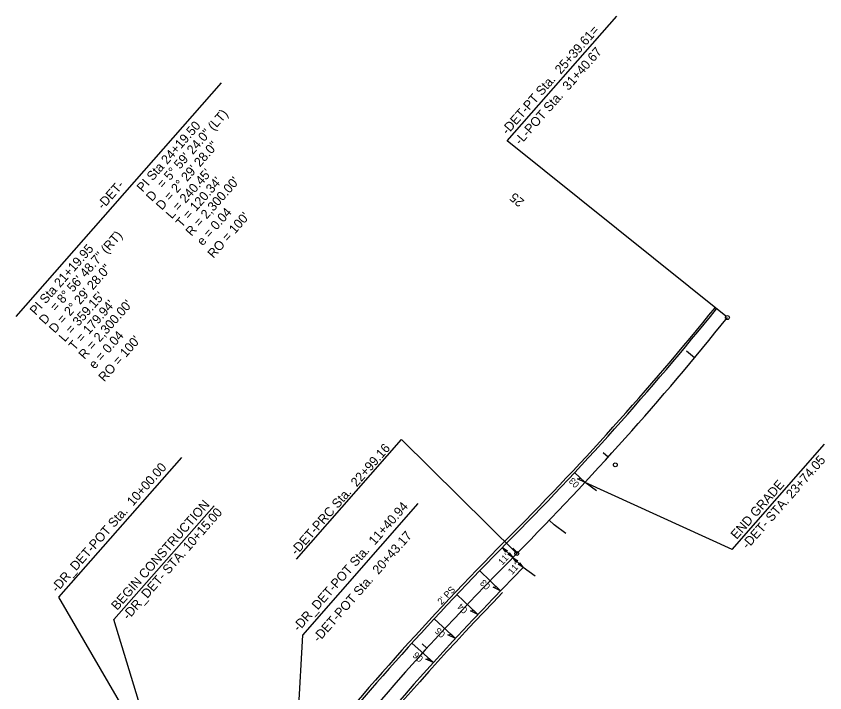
# Model space of a CAD drawing. Extents: x 2189637 to 2190858, y 386969 to 388736.
# Drawn here: x 2190244 to 2190858, y 388222 to 388736 of the extents above; entities that cross this region are included whole.
import ezdxf

# ---------------------------------------------------------------- set-up
doc = ezdxf.new("R2010")
doc.units = 0
for name, color, linetype in [('Exist Environmental Wetland Boundary', 7, 'Continuous'), ('Exist Environmental Wetland Boundary Cogo Comment', 7, 'Continuous'), ('Exist Environmental Wetland Boundary Cogo Point CELL', 7, 'Continuous'), ('Exist Horizontal Alignment Tick Label', 7, 'Continuous'), ('Exist Hydro Stream or Body of Water Leader', 7, 'Continuous'), ('Exist Hydro Swamp or Marsh', 7, 'Continuous'), ('Exist Property Corner CELL', 7, 'Continuous'), ('Exist Property Corner Cogo Elevation', 7, 'Continuous'), ('Exist Property Iron Pin CELL', 7, 'Continuous'), ('Exist Property Iron Pin Cogo Elevation', 7, 'Continuous'), ('Exist Property Iron Pin Cogo Number', 7, 'Continuous'), ('Exist Property Iron Pin Text', 7, 'Continuous'), ('Exist Roads EOP', 7, 'Continuous'), ('Exist Roads EOT', 7, 'Continuous'), ('Exist Roads Soil', 7, 'Continuous'), ('Prop Parcel Number Text', 7, 'Continuous')]:
    doc.layers.add(name, color=color, linetype=linetype)

msp = doc.modelspace()

# ---------------------------------------------------------------- linework, layer by layer
at = {"layer": 'Exist Environmental Wetland Boundary'}
msp.add_line((2190243.96, 388508.09), (2190399.95, 388685.52), dxfattribs=at)
at = {"layer": 'Exist Environmental Wetland Boundary Cogo Comment'}
for p, q in [((2190685.02, 388375.58), (2190676.22, 388381.92)), ((2190649.01, 388353.11), (2190652.7, 388349.56)), ((2190649.01, 388353.11), (2190652.7, 388349.56)), ((2190661.63, 388343.13), (2190652.7, 388349.56)), ((2190638.23, 388310.69), (2190629.25, 388317.16))]:
    msp.add_line(p, q, dxfattribs=at)
at = {"layer": 'Exist Environmental Wetland Boundary Cogo Point CELL'}
for centre, start, end in [((2188990.81, 389946.97), 315.25499, 321.24499), ((2192257.95, 386708.79), 135.25499, 144.20184)]:
    msp.add_arc(centre, 2300, start, end, dxfattribs=at)
at = {"layer": 'Exist Horizontal Alignment Tick Label'}
for p, q in [((2190693.78, 388401.04), (2190690.07, 388404.4)), ((2190624.97, 388328.48), (2190621.42, 388332)), ((2190556.12, 388255.97), (2190552.42, 388259.33))]:
    msp.add_line(p, q, dxfattribs=at)
at = {"layer": 'Exist Hydro Stream or Body of Water Leader'}
msp.add_line((2190759.36, 388476.52), (2190753.21, 388481.63), dxfattribs=at)
at = {"layer": 'Exist Hydro Swamp or Marsh'}
for centre, radius, start, end in [((2188993.22, 389949.67), 2289.19, 315.16471, 321.15472), ((2192257.95, 386708.79), 2311, 135.25499, 141.00543), ((2192257.95, 386708.79), 2289, 135.35973, 144.20184)]:
    msp.add_arc(centre, radius, start, end, dxfattribs=at)
at = {"layer": 'Exist Property Corner CELL'}
for centre, radius, start, end in [((2188997.2, 389954.14), 2287.53, 315.01487, 321.00487), ((2192257.95, 386708.79), 2313, 135.25499, 141.26353), ((2192257.95, 386708.79), 2287, 135.97689, 144.20184)]:
    msp.add_arc(centre, radius, start, end, dxfattribs=at)
at = {"layer": 'Exist Property Corner Cogo Elevation'}
for p, q in [((2190617.16, 388641.46), (2190700.48, 388736.24)), ((2190783.25, 388508.13), (2190617.16, 388641.46)), ((2190457.01, 388323.63), (2190536.81, 388414.4)), ((2190536.81, 388414.4), (2190624.38, 388327.88)), ((2190276.32, 388294.58), (2190369.79, 388400.9)), ((2190461.68, 388265.94), (2190549.51, 388365.85)), ((2190330.06, 388202.3), (2190276.32, 388294.58)), ((2190454.65, 388136.42), (2190461.68, 388265.94))]:
    msp.add_line(p, q, dxfattribs=at)
for centre in [(2190784.42, 388507.19), (2190699.23, 388395.27), (2190624.38, 388327.88)]:
    msp.add_circle(centre, 1.5, dxfattribs=at)
at = {"layer": 'Exist Property Iron Pin CELL'}
for q in [(2190858.29, 388410.94), (2190676.22, 388381.92)]:
    msp.add_line((2190787.93, 388330.91), q, dxfattribs=at)
at = {"layer": 'Exist Property Iron Pin Cogo Elevation'}
for p, q in [((2190668.26, 388389.34), (2190676.22, 388381.92)), ((2190612.02, 388299.53), (2190596.2, 388314.81)), ((2190578.84, 388296.66), (2190594.83, 388281.54)), ((2190561.68, 388278.31), (2190577.83, 388263.37)), ((2190544.72, 388259.78), (2190561.03, 388245.02))]:
    msp.add_line(p, q, dxfattribs=at)
for points in [[(2190676.22, 388381.92), (2190670.47, 388384.55), (2190672.84, 388385.07)], [(2190612.02, 388299.53), (2190606.32, 388302.26), (2190608.69, 388302.74)], [(2190594.83, 388281.54), (2190589.09, 388284.21), (2190591.47, 388284.72)], [(2190577.83, 388263.37), (2190572.07, 388265.98), (2190574.44, 388266.51)], [(2190561.03, 388245.02), (2190555.24, 388247.56), (2190557.6, 388248.12)]]:
    msp.add_lwpolyline(points, close=True, dxfattribs=at)
at = {"layer": 'Exist Property Iron Pin Cogo Number'}
msp.add_lwpolyline([(2190343.32, 388195.29), (2190318.28, 388277.7), (2190394.34, 388364.21)], dxfattribs=at)
at = {"layer": 'Exist Roads EOP'}
for p, q in [((2190613.44, 388332.46), (2190621.34, 388324.81)), ((2190621.34, 388324.81), (2190629.25, 388317.16))]:
    msp.add_line(p, q, dxfattribs=at)
at = {"layer": 'Exist Roads Soil'}
for points in [[(2190616.13, 388328.77), (2190613.44, 388332.46), (2190617.24, 388329.89), (2190616.28, 388329.71)], [(2190618.65, 388328.5), (2190621.34, 388324.81), (2190617.53, 388327.38), (2190618.5, 388327.56)], [(2190624.04, 388321.12), (2190621.34, 388324.81), (2190625.15, 388322.24), (2190624.18, 388322.06)], [(2190626.55, 388320.85), (2190629.25, 388317.16), (2190625.44, 388319.73), (2190626.41, 388319.91)]]:
    msp.add_lwpolyline(points, close=True, dxfattribs=at)

# ---------------------------------------------------------------- texts
at = {"layer": 'Exist Environmental Wetland Boundary'}
for s, p in [('= 5%%d 59\' 24.0" (LT)', (2190355.46, 388604.79)), ('PI Sta 24+19.50', (2190340.13, 388602.05)), ('D = 2%%d 29\' 28.0"', (2190354.71, 388588.34)), ("L = 240.45'", (2190362.22, 388581.73)), ("T = 120.34'", (2190369.73, 388575.13)), ("R = 2,300.00'", (2190377.24, 388568.53)), ('-DET-', (2190309.97, 388588.91)), ('D', (2190347.2, 388594.94)), ('e = 0.04', (2190385.7, 388561.25)), ("RO = 100'", (2190393.9, 388551.79)), ('= 8%%d 56\' 48.7" (RT)', (2190274.14, 388511.28)), ('PI Sta 21+19.95', (2190258.81, 388508.54)), ('D = 2%%d 29\' 28.0"', (2190273.38, 388494.83)), ("L = 359.15'", (2190280.89, 388488.22)), ("T = 179.94'", (2190288.4, 388481.62)), ("R = 2,300.00'", (2190295.91, 388475.02)), ('D', (2190265.87, 388501.43)), ('e = 0.04', (2190303.61, 388467.6)), ("RO = 100'", (2190311, 388457.9))]:
    msp.add_text(s, height=7, rotation=48.67944, dxfattribs=at).set_placement(p)
at = {"layer": 'Exist Property Corner Cogo Elevation'}
for s, p in [('-DET-PT Sta.  25+39.61=', (2190617.27, 388645.61)), ('-L-POT Sta.  31+40.67', (2190627.2, 388637.88)), ('-DET-PRC Sta.  22+99.16', (2190457.06, 388326.11)), ('-DR_DET-POT Sta.  10+00.00', (2190275.05, 388297.89)), ('-DR_DET-POT Sta.  11+40.94', (2190458.68, 388268.13)), ('-DET-POT Sta.  20+43.17', (2190473.9, 388259.94))]:
    msp.add_text(s, height=7, rotation=48.67944, dxfattribs=at).set_placement(p)
at = {"layer": 'Exist Property Iron Pin CELL'}
for s, p in [('-DET- STA. 23+74.05', (2190799.82, 388330.8)), ('END GRADE', (2190791.41, 388338.19))]:
    msp.add_text(s, height=7, rotation=48.67944, dxfattribs=at).set_placement(p)
at = {"layer": 'Exist Property Iron Pin Cogo Number'}
for s, p in [('BEGIN CONSTRUCTION', (2190320.74, 388284.26)), ('-DR_DET- STA. 10+15.00', (2190329.15, 388276.87))]:
    msp.add_text(s, height=7, rotation=48.67944, dxfattribs=at).set_placement(p)
at = {"layer": 'Exist Property Iron Pin Text'}
msp.add_text('25', height=7, rotation=140.25814, dxfattribs=at).set_placement((2190630.62, 388595.94))
at = {"layer": 'Exist Roads EOT'}
for s, rotation, p in [("11'", 47.75673, (2190613.41, 388318.65)), ("11'", 47.75673, (2190620.83, 388311.46)), ("2' PS", 46.6532, (2190567.17, 388288.56))]:
    msp.add_text(s, height=5, rotation=rotation, dxfattribs=at).set_placement(p)
at = {"layer": 'Prop Parcel Number Text'}
for s, rotation, p in [('03', 135.25499, (2190672.27, 388380.78)), ('03', 136.00212, (2190604.74, 388303.33)), ('04', 136.6249, (2190587.48, 388285.28)), ('05', 137.24768, (2190570.47, 388267.01)), ('06', 137.87046, (2190553.7, 388248.52))]:
    msp.add_text(s, height=5, rotation=rotation, dxfattribs=at).set_placement(p)

doc.saveas('drawing.dxf')
